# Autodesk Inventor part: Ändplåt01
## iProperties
Created: 2001-12
Part Number: Ändplåt01
Material: Steel, Mild
Document SubType Name: Modeling
Designer: Tobben
Control State: 0
Master: False
Checked Out: False
Shininess: 64.0
Length Units: 11269
Angle Units: 11279
Time Units: 11290
Mass Units: 11283
Length Display Precision: 3
Angle Display Precision: 2
Density: 0.0
Volumn: 0.0
Area: 0.0
PropertySet Name: Model Information
Author: Tobben
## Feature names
1. Extrusion1
